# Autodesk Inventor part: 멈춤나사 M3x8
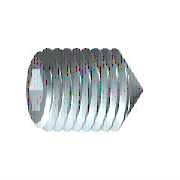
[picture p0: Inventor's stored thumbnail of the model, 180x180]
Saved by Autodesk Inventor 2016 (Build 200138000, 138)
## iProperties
IsCustomPart: 1
Created: 2012-02
Part Number: 멈춤나사 M3x8
Material: 강철, 연강
Description: 6각 소켓 머리 없는 멈춤 나사
Document SubType Name: Modeling
Standard: KS B 1028
Designer: test
Standards Organization: KS
Language: ko-KR
Size Designation: 원추점 M3x8
Categories: <MemberInstance><Categories><Category DisplayName="조임쇠" InternalName="e4da775c-781d-43d5-af7c-5136215cf5a6" Mnemonic="FSTN"><Category DisplayName="볼트" InternalN
Density: 1 g/cm^3
Appearance: 강철
Author: test
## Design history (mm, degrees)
sketch "스케치1"
  geometry: L1 (0, 0)-(5.5, 0); L2 (8, 0.866)-(8, 1.5); L3 (8, 1.5)-(0, 1.5); L4 (8, 0.866)-(6, 0.866); L5 (6, 0.866)-(5.5, 0); L6 (0, -0.3)-(0, 1.8) reference; L7 (0, 1.5)-(0, 0)
  constraints: 13 end point, 3 parallel, 1 collinear, 1 perpendicular, 1 point on line
  dimensions: "d0" = 2 distance of L2.start L4.end (= INTI); "d1" = 60 deg angle of L5 L1; "d2" = 3 diameter of L3 L1 (= NND); "d3" = 1.73205 diameter of L4 L1 (= 1.1547 x SW); "d5" = 8 distance from line of L2 L3.end (= NLG)
revolve "본체" sketch "스케치1" stored, may be unused: angle "d6" = 90 deg
sketch "스케치2"
  geometry: L1 (-0.433, 0.75)-(0.433, 0.75); L2 (0.433, 0.75)-(0.866, 0); L3 (0.866, 0)-(0.433, -0.75); L4 (0.433, -0.75)-(-0.433, -0.75); L5 (-0.433, -0.75)-(-0.866, 0); L6 (-0.866, 0)-(-0.433, 0.75); 3 further points
  constraints: 12 end point, 1 coincident, 1 horizontal, 13 other
extrude "슬롯" join sketch "스케치2" taper "d7" = 0 deg; stored distance "d21" = 10
workaxis "Work Axis1"
workplane "Work Plane1"
sketch "스케치4"
  geometry: L1 (0, 0.15)-(-1.35, 1.5) reference; L2 (0, -0.15)-(-1.35, -1.5) reference; L3 (-1.35, -1.5)-(0.15, 0); L4 (-1.35, 1.5)-(0.15, 0); 2 further points
  constraints: 4 end point, 1 coincident, 1 collinear, 1 horizontal alignment
node "작업 평면2"
body "Solid1"
feature "스레드" dims "d12" = 8 (= NLG), "d13" = 0
chamfer "모따기1" distance "d8" = 1.35 (computed from NND, SPD, FAWI); stored, may be unused: angle "d9" = 45 deg (= FAWI), second distance "d34" = 1.35 (computed from NND, SPD, FAWI)
chamfer "모따기2" distance "d10" = 0.30673 (= -0.5 x GD1 + 0.5 x NND); stored, may be unused: angle "d11" = 45 deg (= FAWI), second distance "d35" = 0.30673 (= -0.5 x GD1 + 0.5 x NND)
other parameters: "NND" = 3 [user parameter; used in 5 equation terms], "NLG" = 8 [user parameter; used in 2 equation terms], "INTI" = 2 [user parameter; used in 1 equation term], "FAWI" = 45 deg [user parameter; used in 4 equation terms], "SW" = 1.5 [user parameter; used in 2 equation terms], "GD1" = 2.38655 (= THREADDIA - 1.2269 x PTC) [user parameter; used in 2 equation terms], "d4" = 0, "FAWI1" = 45 deg [user parameter], "SPD" = 0.3 [user parameter; used in 2 equation terms], "d36" = 0, "d37" = 0, "GUL" = 0.30673 (= 0.61345 x PTC) [user parameter], "TOA" = 30 deg [user parameter], "THREADDIA" = 3 [user parameter; used in 1 equation term], "PTC" = 0.5 [user parameter; used in 4 equation terms], "GAL" = 0.30673 (= 0.61345 x PTC) [user parameter], "E0" = 1.7325 (= 1.155 x SW) [user parameter], "d38" = 1.35
